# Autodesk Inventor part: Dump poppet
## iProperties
Created: 2008-09
Part Number: Dump poppet
Document SubType Name: Modeling
Designer: the-dude
Density: 1 g/cm^3
Material: Default
Mass: 14.8413 g
Surface Area: 75.3896 cm^2
Volume: 14.8413 cm^3
Author: the-dude
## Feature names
1. Poppet outline [Revolution]
2. Input port [Revolution]
3. Input ports array [Circular Pattern]
4. Extrusion2
5. Circular Pattern2
